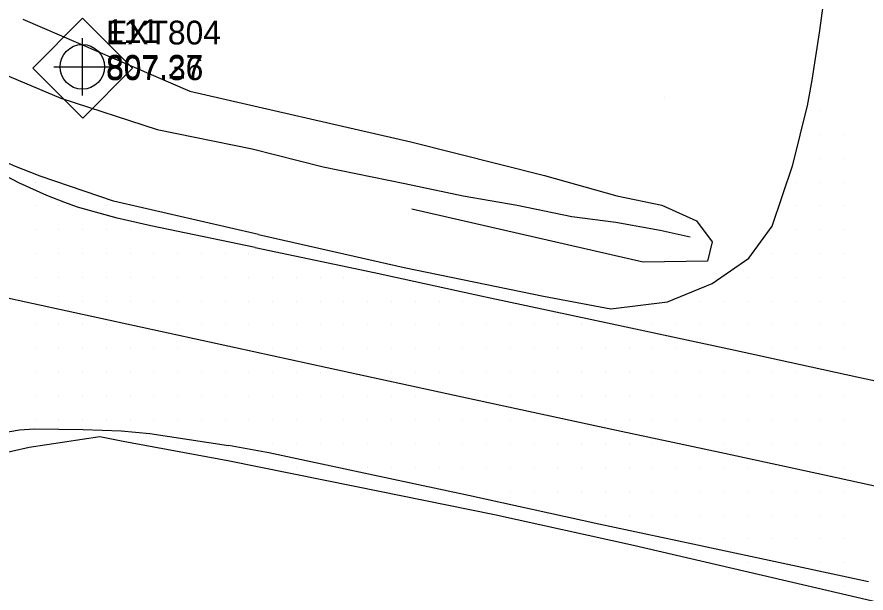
# Model space of a CAD drawing. Extents: x 1762120 to 1766775, y 709485 to 712965.
# Drawn here: x 1763911.9 to 1764001.2, y 712368.1 to 712428.6 of the extents above; entities that cross this region are included whole.
import ezdxf

# ---------------------------------------------------------------- set-up
doc = ezdxf.new("R2010")
doc.units = 0
for name, color, linetype in [('Cogo Default Point CELL', 7, 'Continuous'), ('COGO Default Point Elevation', 7, 'Continuous'), ('COGO Default Point Number', 7, 'Continuous'), ('CTL Secondary Horizontal and Vertical CELL', 7, 'Continuous'), ('CTL Secondary Horizontal and Vertical Cogo Elevation', 7, 'Continuous'), ('CTL Secondary Horizontal and Vertical Cogo Number', 7, 'Continuous'), ('Exist DTM QL2 LIDAR Elevation Point', 7, 'Continuous'), ('Exist DTM Scan Elevation Point', 7, 'Continuous'), ('Exist Roads EOP', 7, 'Continuous'), ('Exist Roads EOT', 7, 'Continuous'), ('PH Exist DTM Breakline', 7, 'Continuous')]:
    doc.layers.add(name, color=color, linetype=linetype)

msp = doc.modelspace()

# ---------------------------------------------------------------- linework, layer by layer
at = {"layer": 'Cogo Default Point CELL'}
for points in [[(1763918.724, 712426.379), (1763918.724, 712423.379)], [(1763915.724, 712423.379), (1763918.724, 712423.379)], [(1763918.724, 712423.379), (1763921.724, 712423.379)], [(1763918.724, 712423.379), (1763918.724, 712420.379)]]:
    msp.add_lwpolyline(points, dxfattribs=at)
msp.add_circle((1763918.724, 712423.379), 2.344, dxfattribs=at)
at = {"layer": 'CTL Secondary Horizontal and Vertical CELL'}
msp.add_line((1763918.73, 712423.23), (1763918.73, 712423.23), dxfattribs=at)
msp.add_lwpolyline([(1763913.515, 712423.248), (1763918.757, 712428.489), (1763924.007, 712423.239), (1763918.765, 712417.997)], close=True, dxfattribs=at)
at = {"layer": 'Exist DTM QL2 LIDAR Elevation Point'}
msp.add_line((1763979.981, 712420.146), (1763979.981, 712420.146), dxfattribs=at)
at = {"layer": 'Exist DTM Scan Elevation Point'}
for p, q in [((1763996.25, 712418.75), (1763996.25, 712418.75)), ((1763996.25, 712416.25), (1763996.25, 712416.25)), ((1763998.75, 712416.25), (1763998.75, 712416.25)), ((1763996.25, 712413.75), (1763996.25, 712413.75)), ((1763998.75, 712413.75), (1763998.75, 712413.75)), ((1763913.75, 712411.25), (1763913.75, 712411.25)), ((1763993.75, 712411.25), (1763993.75, 712411.25)), ((1763996.25, 712411.25), (1763996.25, 712411.25)), ((1763998.75, 712411.25), (1763998.75, 712411.25)), ((1763913.75, 712408.75), (1763913.75, 712408.75)), ((1763916.25, 712408.75), (1763916.25, 712408.75)), ((1763921.25, 712408.75), (1763921.25, 712408.75)), ((1763993.75, 712408.75), (1763993.75, 712408.75)), ((1763996.25, 712408.75), (1763996.25, 712408.75)), ((1763998.75, 712408.75), (1763998.75, 712408.75)), ((1763913.75, 712406.25), (1763913.75, 712406.25)), ((1763916.25, 712406.25), (1763916.25, 712406.25)), ((1763918.75, 712406.25), (1763918.75, 712406.25)), ((1763921.25, 712406.25), (1763921.25, 712406.25)), ((1763923.75, 712406.25), (1763923.75, 712406.25)), ((1763931.25, 712406.25), (1763931.25, 712406.25)), ((1763993.75, 712406.25), (1763993.75, 712406.25)), ((1763996.25, 712406.25), (1763996.25, 712406.25)), ((1763998.75, 712406.25), (1763998.75, 712406.25)), ((1763913.75, 712403.75), (1763913.75, 712403.75)), ((1763916.25, 712403.75), (1763916.25, 712403.75)), ((1763918.75, 712403.75), (1763918.75, 712403.75)), ((1763921.25, 712403.75), (1763921.25, 712403.75)), ((1763923.75, 712403.75), (1763923.75, 712403.75)), ((1763926.25, 712403.75), (1763926.25, 712403.75)), ((1763928.75, 712403.75), (1763928.75, 712403.75)), ((1763931.25, 712403.75), (1763931.25, 712403.75)), ((1763933.75, 712403.75), (1763933.75, 712403.75)), ((1763936.25, 712403.75), (1763936.25, 712403.75)), ((1763943.75, 712403.75), (1763943.75, 712403.75)), ((1763991.25, 712403.75), (1763991.25, 712403.75)), ((1763993.75, 712403.75), (1763993.75, 712403.75)), ((1763996.25, 712403.75), (1763996.25, 712403.75)), ((1763998.75, 712403.75), (1763998.75, 712403.75)), ((1763913.75, 712401.25), (1763913.75, 712401.25)), ((1763916.25, 712401.25), (1763916.25, 712401.25)), ((1763918.75, 712401.25), (1763918.75, 712401.25)), ((1763921.25, 712401.25), (1763921.25, 712401.25)), ((1763923.75, 712401.25), (1763923.75, 712401.25)), ((1763926.25, 712401.25), (1763926.25, 712401.25)), ((1763928.75, 712401.25), (1763928.75, 712401.25)), ((1763931.25, 712401.25), (1763931.25, 712401.25)), ((1763933.75, 712401.25), (1763933.75, 712401.25)), ((1763936.25, 712401.25), (1763936.25, 712401.25)), ((1763938.75, 712401.25), (1763938.75, 712401.25)), ((1763941.25, 712401.25), (1763941.25, 712401.25)), ((1763943.75, 712401.25), (1763943.75, 712401.25)), ((1763946.25, 712401.25), (1763946.25, 712401.25)), ((1763948.75, 712401.25), (1763948.75, 712401.25)), ((1763988.75, 712401.25), (1763988.75, 712401.25)), ((1763991.25, 712401.25), (1763991.25, 712401.25)), ((1763993.75, 712401.25), (1763993.75, 712401.25)), ((1763996.25, 712401.25), (1763996.25, 712401.25)), ((1763998.75, 712401.25), (1763998.75, 712401.25)), ((1763916.25, 712398.75), (1763916.25, 712398.75)), ((1763918.75, 712398.75), (1763918.75, 712398.75)), ((1763921.25, 712398.75), (1763921.25, 712398.75)), ((1763923.75, 712398.75), (1763923.75, 712398.75)), ((1763926.25, 712398.75), (1763926.25, 712398.75)), ((1763928.75, 712398.75), (1763928.75, 712398.75)), ((1763931.25, 712398.75), (1763931.25, 712398.75)), ((1763933.75, 712398.75), (1763933.75, 712398.75)), ((1763936.25, 712398.75), (1763936.25, 712398.75)), ((1763938.75, 712398.75), (1763938.75, 712398.75)), ((1763941.25, 712398.75), (1763941.25, 712398.75)), ((1763943.75, 712398.75), (1763943.75, 712398.75)), ((1763946.25, 712398.75), (1763946.25, 712398.75)), ((1763948.75, 712398.75), (1763948.75, 712398.75)), ((1763951.25, 712398.75), (1763951.25, 712398.75)), ((1763953.75, 712398.75), (1763953.75, 712398.75)), ((1763956.25, 712398.75), (1763956.25, 712398.75)), ((1763958.75, 712398.75), (1763958.75, 712398.75)), ((1763966.25, 712398.75), (1763966.25, 712398.75)), ((1763983.75, 712398.75), (1763983.75, 712398.75)), ((1763986.25, 712398.75), (1763986.25, 712398.75)), ((1763988.75, 712398.75), (1763988.75, 712398.75)), ((1763991.25, 712398.75), (1763991.25, 712398.75)), ((1763993.75, 712398.75), (1763993.75, 712398.75)), ((1763996.25, 712398.75), (1763996.25, 712398.75)), ((1763998.75, 712398.75), (1763998.75, 712398.75)), ((1763913.75, 712396.25), (1763913.75, 712396.25)), ((1763916.25, 712396.25), (1763916.25, 712396.25)), ((1763918.75, 712396.25), (1763918.75, 712396.25)), ((1763921.25, 712396.25), (1763921.25, 712396.25)), ((1763928.75, 712396.25), (1763928.75, 712396.25)), ((1763931.25, 712396.25), (1763931.25, 712396.25)), ((1763933.75, 712396.25), (1763933.75, 712396.25)), ((1763936.25, 712396.25), (1763936.25, 712396.25)), ((1763938.75, 712396.25), (1763938.75, 712396.25)), ((1763941.25, 712396.25), (1763941.25, 712396.25)), ((1763943.75, 712396.25), (1763943.75, 712396.25)), ((1763946.25, 712396.25), (1763946.25, 712396.25)), ((1763948.75, 712396.25), (1763948.75, 712396.25)), ((1763951.25, 712396.25), (1763951.25, 712396.25)), ((1763953.75, 712396.25), (1763953.75, 712396.25)), ((1763956.25, 712396.25), (1763956.25, 712396.25)), ((1763958.75, 712396.25), (1763958.75, 712396.25)), ((1763961.25, 712396.25), (1763961.25, 712396.25)), ((1763963.75, 712396.25), (1763963.75, 712396.25)), ((1763966.25, 712396.25), (1763966.25, 712396.25)), ((1763968.75, 712396.25), (1763968.75, 712396.25)), ((1763971.25, 712396.25), (1763971.25, 712396.25)), ((1763978.75, 712396.25), (1763978.75, 712396.25)), ((1763981.25, 712396.25), (1763981.25, 712396.25)), ((1763983.75, 712396.25), (1763983.75, 712396.25)), ((1763986.25, 712396.25), (1763986.25, 712396.25)), ((1763988.75, 712396.25), (1763988.75, 712396.25)), ((1763991.25, 712396.25), (1763991.25, 712396.25)), ((1763993.75, 712396.25), (1763993.75, 712396.25)), ((1763996.25, 712396.25), (1763996.25, 712396.25)), ((1763998.75, 712396.25), (1763998.75, 712396.25)), ((1763913.75, 712393.75), (1763913.75, 712393.75)), ((1763916.25, 712393.75), (1763916.25, 712393.75)), ((1763918.75, 712393.75), (1763918.75, 712393.75)), ((1763921.25, 712393.75), (1763921.25, 712393.75)), ((1763923.75, 712393.75), (1763923.75, 712393.75)), ((1763926.25, 712393.75), (1763926.25, 712393.75)), ((1763928.75, 712393.75), (1763928.75, 712393.75)), ((1763931.25, 712393.75), (1763931.25, 712393.75)), ((1763938.75, 712393.75), (1763938.75, 712393.75)), ((1763941.25, 712393.75), (1763941.25, 712393.75)), ((1763943.75, 712393.75), (1763943.75, 712393.75)), ((1763946.25, 712393.75), (1763946.25, 712393.75)), ((1763948.75, 712393.75), (1763948.75, 712393.75)), ((1763951.25, 712393.75), (1763951.25, 712393.75)), ((1763953.75, 712393.75), (1763953.75, 712393.75)), ((1763956.25, 712393.75), (1763956.25, 712393.75)), ((1763958.75, 712393.75), (1763958.75, 712393.75)), ((1763961.25, 712393.75), (1763961.25, 712393.75)), ((1763963.75, 712393.75), (1763963.75, 712393.75)), ((1763966.25, 712393.75), (1763966.25, 712393.75)), ((1763968.75, 712393.75), (1763968.75, 712393.75)), ((1763971.25, 712393.75), (1763971.25, 712393.75)), ((1763973.75, 712393.75), (1763973.75, 712393.75)), ((1763976.25, 712393.75), (1763976.25, 712393.75)), ((1763978.75, 712393.75), (1763978.75, 712393.75)), ((1763981.25, 712393.75), (1763981.25, 712393.75)), ((1763983.75, 712393.75), (1763983.75, 712393.75)), ((1763991.25, 712393.75), (1763991.25, 712393.75)), ((1763993.75, 712393.75), (1763993.75, 712393.75)), ((1763996.25, 712393.75), (1763996.25, 712393.75)), ((1763998.75, 712393.75), (1763998.75, 712393.75)), ((1763913.75, 712391.25), (1763913.75, 712391.25)), ((1763916.25, 712391.25), (1763916.25, 712391.25)), ((1763918.75, 712391.25), (1763918.75, 712391.25)), ((1763921.25, 712391.25), (1763921.25, 712391.25)), ((1763923.75, 712391.25), (1763923.75, 712391.25)), ((1763926.25, 712391.25), (1763926.25, 712391.25)), ((1763928.75, 712391.25), (1763928.75, 712391.25)), ((1763931.25, 712391.25), (1763931.25, 712391.25)), ((1763933.75, 712391.25), (1763933.75, 712391.25)), ((1763936.25, 712391.25), (1763936.25, 712391.25)), ((1763938.75, 712391.25), (1763938.75, 712391.25)), ((1763941.25, 712391.25), (1763941.25, 712391.25)), ((1763943.75, 712391.25), (1763943.75, 712391.25)), ((1763951.25, 712391.25), (1763951.25, 712391.25)), ((1763953.75, 712391.25), (1763953.75, 712391.25)), ((1763956.25, 712391.25), (1763956.25, 712391.25)), ((1763958.75, 712391.25), (1763958.75, 712391.25)), ((1763961.25, 712391.25), (1763961.25, 712391.25)), ((1763963.75, 712391.25), (1763963.75, 712391.25)), ((1763966.25, 712391.25), (1763966.25, 712391.25)), ((1763968.75, 712391.25), (1763968.75, 712391.25)), ((1763971.25, 712391.25), (1763971.25, 712391.25)), ((1763973.75, 712391.25), (1763973.75, 712391.25)), ((1763976.25, 712391.25), (1763976.25, 712391.25)), ((1763978.75, 712391.25), (1763978.75, 712391.25)), ((1763981.25, 712391.25), (1763981.25, 712391.25)), ((1763983.75, 712391.25), (1763983.75, 712391.25)), ((1763986.25, 712391.25), (1763986.25, 712391.25)), ((1763988.75, 712391.25), (1763988.75, 712391.25)), ((1763991.25, 712391.25), (1763991.25, 712391.25)), ((1763993.75, 712391.25), (1763993.75, 712391.25)), ((1763913.75, 712388.75), (1763913.75, 712388.75)), ((1763916.25, 712388.75), (1763916.25, 712388.75)), ((1763918.75, 712388.75), (1763918.75, 712388.75)), ((1763921.25, 712388.75), (1763921.25, 712388.75)), ((1763923.75, 712388.75), (1763923.75, 712388.75)), ((1763926.25, 712388.75), (1763926.25, 712388.75)), ((1763928.75, 712388.75), (1763928.75, 712388.75)), ((1763931.25, 712388.75), (1763931.25, 712388.75)), ((1763933.75, 712388.75), (1763933.75, 712388.75)), ((1763936.25, 712388.75), (1763936.25, 712388.75)), ((1763938.75, 712388.75), (1763938.75, 712388.75)), ((1763941.25, 712388.75), (1763941.25, 712388.75)), ((1763943.75, 712388.75), (1763943.75, 712388.75)), ((1763946.25, 712388.75), (1763946.25, 712388.75)), ((1763948.75, 712388.75), (1763948.75, 712388.75)), ((1763951.25, 712388.75), (1763951.25, 712388.75)), ((1763953.75, 712388.75), (1763953.75, 712388.75)), ((1763961.25, 712388.75), (1763961.25, 712388.75)), ((1763963.75, 712388.75), (1763963.75, 712388.75)), ((1763966.25, 712388.75), (1763966.25, 712388.75)), ((1763968.75, 712388.75), (1763968.75, 712388.75)), ((1763971.25, 712388.75), (1763971.25, 712388.75)), ((1763973.75, 712388.75), (1763973.75, 712388.75)), ((1763976.25, 712388.75), (1763976.25, 712388.75)), ((1763978.75, 712388.75), (1763978.75, 712388.75)), ((1763981.25, 712388.75), (1763981.25, 712388.75)), ((1763983.75, 712388.75), (1763983.75, 712388.75)), ((1763986.25, 712388.75), (1763986.25, 712388.75)), ((1763988.75, 712388.75), (1763988.75, 712388.75)), ((1763991.25, 712388.75), (1763991.25, 712388.75)), ((1763993.75, 712388.75), (1763993.75, 712388.75)), ((1763996.25, 712388.75), (1763996.25, 712388.75)), ((1763998.75, 712388.75), (1763998.75, 712388.75)), ((1763913.75, 712386.25), (1763913.75, 712386.25)), ((1763916.25, 712386.25), (1763916.25, 712386.25)), ((1763918.75, 712386.25), (1763918.75, 712386.25)), ((1763921.25, 712386.25), (1763921.25, 712386.25)), ((1763923.75, 712386.25), (1763923.75, 712386.25)), ((1763926.25, 712386.25), (1763926.25, 712386.25)), ((1763928.75, 712386.25), (1763928.75, 712386.25)), ((1763931.25, 712386.25), (1763931.25, 712386.25)), ((1763933.75, 712386.25), (1763933.75, 712386.25)), ((1763936.25, 712386.25), (1763936.25, 712386.25)), ((1763938.75, 712386.25), (1763938.75, 712386.25)), ((1763941.25, 712386.25), (1763941.25, 712386.25)), ((1763943.75, 712386.25), (1763943.75, 712386.25)), ((1763946.25, 712386.25), (1763946.25, 712386.25)), ((1763948.75, 712386.25), (1763948.75, 712386.25)), ((1763951.25, 712386.25), (1763951.25, 712386.25)), ((1763953.75, 712386.25), (1763953.75, 712386.25)), ((1763956.25, 712386.25), (1763956.25, 712386.25)), ((1763958.75, 712386.25), (1763958.75, 712386.25)), ((1763961.25, 712386.25), (1763961.25, 712386.25)), ((1763963.75, 712386.25), (1763963.75, 712386.25)), ((1763966.25, 712386.25), (1763966.25, 712386.25)), ((1763973.75, 712386.25), (1763973.75, 712386.25)), ((1763976.25, 712386.25), (1763976.25, 712386.25)), ((1763978.75, 712386.25), (1763978.75, 712386.25)), ((1763981.25, 712386.25), (1763981.25, 712386.25)), ((1763983.75, 712386.25), (1763983.75, 712386.25)), ((1763986.25, 712386.25), (1763986.25, 712386.25)), ((1763988.75, 712386.25), (1763988.75, 712386.25)), ((1763991.25, 712386.25), (1763991.25, 712386.25)), ((1763993.75, 712386.25), (1763993.75, 712386.25)), ((1763996.25, 712386.25), (1763996.25, 712386.25)), ((1763998.75, 712386.25), (1763998.75, 712386.25)), ((1763928.75, 712383.75), (1763928.75, 712383.75)), ((1763936.25, 712383.75), (1763936.25, 712383.75)), ((1763938.75, 712383.75), (1763938.75, 712383.75)), ((1763941.25, 712383.75), (1763941.25, 712383.75)), ((1763943.75, 712383.75), (1763943.75, 712383.75)), ((1763946.25, 712383.75), (1763946.25, 712383.75)), ((1763948.75, 712383.75), (1763948.75, 712383.75)), ((1763951.25, 712383.75), (1763951.25, 712383.75)), ((1763953.75, 712383.75), (1763953.75, 712383.75)), ((1763956.25, 712383.75), (1763956.25, 712383.75)), ((1763958.75, 712383.75), (1763958.75, 712383.75)), ((1763961.25, 712383.75), (1763961.25, 712383.75)), ((1763963.75, 712383.75), (1763963.75, 712383.75)), ((1763966.25, 712383.75), (1763966.25, 712383.75)), ((1763968.75, 712383.75), (1763968.75, 712383.75)), ((1763971.25, 712383.75), (1763971.25, 712383.75)), ((1763973.75, 712383.75), (1763973.75, 712383.75)), ((1763976.25, 712383.75), (1763976.25, 712383.75)), ((1763978.75, 712383.75), (1763978.75, 712383.75)), ((1763986.25, 712383.75), (1763986.25, 712383.75)), ((1763988.75, 712383.75), (1763988.75, 712383.75)), ((1763991.25, 712383.75), (1763991.25, 712383.75)), ((1763993.75, 712383.75), (1763993.75, 712383.75)), ((1763996.25, 712383.75), (1763996.25, 712383.75)), ((1763998.75, 712383.75), (1763998.75, 712383.75)), ((1763941.25, 712381.25), (1763941.25, 712381.25)), ((1763948.75, 712381.25), (1763948.75, 712381.25)), ((1763951.25, 712381.25), (1763951.25, 712381.25)), ((1763953.75, 712381.25), (1763953.75, 712381.25)), ((1763956.25, 712381.25), (1763956.25, 712381.25)), ((1763958.75, 712381.25), (1763958.75, 712381.25)), ((1763961.25, 712381.25), (1763961.25, 712381.25)), ((1763963.75, 712381.25), (1763963.75, 712381.25)), ((1763966.25, 712381.25), (1763966.25, 712381.25)), ((1763968.75, 712381.25), (1763968.75, 712381.25)), ((1763971.25, 712381.25), (1763971.25, 712381.25)), ((1763973.75, 712381.25), (1763973.75, 712381.25)), ((1763976.25, 712381.25), (1763976.25, 712381.25)), ((1763978.75, 712381.25), (1763978.75, 712381.25)), ((1763981.25, 712381.25), (1763981.25, 712381.25)), ((1763983.75, 712381.25), (1763983.75, 712381.25)), ((1763986.25, 712381.25), (1763986.25, 712381.25)), ((1763988.75, 712381.25), (1763988.75, 712381.25)), ((1763996.25, 712381.25), (1763996.25, 712381.25)), ((1763998.75, 712381.25), (1763998.75, 712381.25)), ((1763953.75, 712378.75), (1763953.75, 712378.75)), ((1763961.25, 712378.75), (1763961.25, 712378.75)), ((1763963.75, 712378.75), (1763963.75, 712378.75)), ((1763966.25, 712378.75), (1763966.25, 712378.75)), ((1763968.75, 712378.75), (1763968.75, 712378.75)), ((1763971.25, 712378.75), (1763971.25, 712378.75)), ((1763973.75, 712378.75), (1763973.75, 712378.75)), ((1763976.25, 712378.75), (1763976.25, 712378.75)), ((1763978.75, 712378.75), (1763978.75, 712378.75)), ((1763981.25, 712378.75), (1763981.25, 712378.75)), ((1763983.75, 712378.75), (1763983.75, 712378.75)), ((1763986.25, 712378.75), (1763986.25, 712378.75)), ((1763988.75, 712378.75), (1763988.75, 712378.75)), ((1763991.25, 712378.75), (1763991.25, 712378.75)), ((1763993.75, 712378.75), (1763993.75, 712378.75)), ((1763996.25, 712378.75), (1763996.25, 712378.75)), ((1763998.75, 712378.75), (1763998.75, 712378.75)), ((1763966.25, 712376.25), (1763966.25, 712376.25)), ((1763971.25, 712376.25), (1763971.25, 712376.25)), ((1763973.75, 712376.25), (1763973.75, 712376.25)), ((1763976.25, 712376.25), (1763976.25, 712376.25)), ((1763978.75, 712376.25), (1763978.75, 712376.25)), ((1763981.25, 712376.25), (1763981.25, 712376.25)), ((1763983.75, 712376.25), (1763983.75, 712376.25)), ((1763986.25, 712376.25), (1763986.25, 712376.25)), ((1763988.75, 712376.25), (1763988.75, 712376.25)), ((1763991.25, 712376.25), (1763991.25, 712376.25)), ((1763993.75, 712376.25), (1763993.75, 712376.25)), ((1763996.25, 712376.25), (1763996.25, 712376.25)), ((1763998.75, 712376.25), (1763998.75, 712376.25)), ((1763976.25, 712373.75), (1763976.25, 712373.75)), ((1763983.75, 712373.75), (1763983.75, 712373.75)), ((1763986.25, 712373.75), (1763986.25, 712373.75)), ((1763988.75, 712373.75), (1763988.75, 712373.75)), ((1763991.25, 712373.75), (1763991.25, 712373.75)), ((1763993.75, 712373.75), (1763993.75, 712373.75)), ((1763996.25, 712373.75), (1763996.25, 712373.75)), ((1763998.75, 712373.75), (1763998.75, 712373.75)), ((1763988.75, 712371.25), (1763988.75, 712371.25)), ((1763996.25, 712371.25), (1763996.25, 712371.25)), ((1763998.75, 712371.25), (1763998.75, 712371.25)), ((1763998.75, 712368.75), (1763998.75, 712368.75))]:
    msp.add_line(p, q, dxfattribs=at)
at = {"layer": 'Exist Roads EOP'}
for points in [[(1763937.27, 712405.74), (1763922, 712409.27), (1763914.3, 712411.89), (1763911.52, 712412.97), (1763907.31, 712414.92), (1763905.7, 712415.7), (1763904.88, 712417.5), (1763901.53, 712420.73), (1763892.75, 712429.99), (1763886.13, 712439.51), (1763884.183, 712443.669)], [(1763974.333, 712397.927), (1763980.3, 712398.665), (1763984.997, 712400.593), (1763988.846, 712403.258), (1763991.289, 712406.636), (1763993.481, 712413.079), (1763995.017, 712419.301)], [(1763937.27, 712405.74), (1763952.569, 712402.29), (1763967.246, 712399.269), (1763974.333, 712397.927)], [(1763934.045, 712381.948), (1763923.009, 712384.006), (1763920.567, 712384.464), (1763913.145, 712383.35), (1763909.379, 712382.508), (1763904.066, 712380.959), (1763901.156, 712379.529), (1763899.682, 712377.869), (1763897.304, 712375.885), (1763895.607, 712374.495), (1763894.665, 712373.129), (1763893.725, 712370.718), (1763892.719, 712368.183), (1763892.001, 712365.299), (1763891.368, 712360.754), (1763891.073, 712357.928), (1763891.057, 712351.383)], [(1764064.668, 712330.179), (1764064.854, 712330.245), (1764068.514, 712331.608), (1764069.587, 712332.629), (1764070.141, 712333.86), (1764069.865, 712336.332), (1764069.125, 712339.365), (1764068.178, 712342.188), (1764067.219, 712345.091), (1764065.818, 712347.808), (1764051.04, 712351.71), (1764036.514, 712355.552), (1764028.09, 712358.126), (1764020.547, 712362.975), (1764005.935, 712366.257), (1763991.324, 712369.661), (1763976.724, 712373.072), (1763962.071, 712376.273), (1763947.386, 712379.266), (1763934.045, 712381.948)]]:
    msp.add_lwpolyline(points, dxfattribs=at)
at = {"layer": 'Exist Roads EOT'}
for points in [[(1763936.9, 712404.39), (1763925.94, 712406.66), (1763922.4, 712407.48), (1763918.21, 712408.64), (1763916.89, 712409.12), (1763914.98, 712409.85), (1763912.11, 712411.15), (1763909.8, 712412.34), (1763907.51, 712413.59), (1763902.3, 712417.34), (1763899.48, 712420.04), (1763895.32, 712424.3), (1763892.72, 712427.36), (1763890.75, 712429.87), (1763889.19, 712432.14), (1763886.09, 712437.17), (1763884.49, 712440.43)], [(1763936.9, 712404.39), (1763949.432, 712401.765), (1763961.153, 712399.203), (1763974.456, 712396.373), (1763987.24, 712393.621), (1764000.212, 712390.795), (1764012.465, 712388.156), (1764026.205, 712385.101), (1764037.224, 712382.749), (1764049.265, 712380.14), (1764066.313, 712376.495), (1764083.445, 712372.764), (1764095.454, 712370.149), (1764109.306, 712367.155), (1764120.538, 712364.717), (1764131.502, 712362.333), (1764145.221, 712359.394), (1764154.889, 712357.364), (1764167.863, 712354.686), (1764175.23, 712353.101), (1764183.759, 712351.333), (1764196.566, 712348.502)], [(1763910.03, 712399.26), (1763934.85, 712393.88)], [(1763934.85, 712393.88), (1763944.479, 712391.773), (1763958.695, 712388.702), (1763974.939, 712385.195), (1763986.293, 712382.776), (1763996.812, 712380.495), (1764022.245, 712374.912), (1764038.571, 712371.473), (1764049.555, 712369.081), (1764063.415, 712366.068), (1764079.739, 712362.586), (1764092.609, 712359.852), (1764108.103, 712356.47), (1764121.783, 712353.589), (1764136.909, 712350.3), (1764153.18, 712346.875), (1764169.623, 712343.331), (1764181.305, 712340.815), (1764211.754, 712334.157), (1764222.045, 712332.077)], [(1763894.29, 712375.12), (1763898.67, 712379.54), (1763899.94, 712380.53), (1763904.8, 712383.48), (1763906.8, 712384.13), (1763908.81, 712384.61), (1763910.06, 712384.85), (1763912.13, 712385.21), (1763913.71, 712385.33), (1763918.81, 712385.26), (1763922.82, 712385.1), (1763925.83, 712384.83), (1763934.114, 712383.564)], [(1764001.432, 712369.231), (1763993.43, 712370.947), (1763982.941, 712373.206), (1763973.078, 712375.313), (1763959.351, 712378.302), (1763948.331, 712380.674), (1763938.362, 712382.805), (1763934.114, 712383.564)]]:
    msp.add_lwpolyline(points, dxfattribs=at)
at = {"layer": 'PH Exist DTM Breakline'}
for points in [[(1763887.598, 712457.067), (1763888.297, 712452.424), (1763890.798, 712445.877), (1763893.88, 712438.461), (1763896.87, 712433.203), (1763899.913, 712429.006), (1763902.307, 712426.624), (1763908.119, 712423.59), (1763916.457, 712420.088), (1763926.606, 712416.801), (1763936.591, 712414.759), (1763944.064, 712412.865), (1763952.639, 712411.118), (1763958.807, 712409.813), (1763964.456, 712408.822), (1763970.211, 712407.63), (1763974.866, 712407.043), (1763979.52, 712406.22), (1763982.686, 712405.505)], [(1763995, 712419.265), (1763995.505, 712421.974), (1763996.309, 712427.209), (1763996.852, 712431.121)], [(1763912.454, 712428.378), (1763930.048, 712420.835), (1763953.297, 712415.494), (1763967.361, 712411.955), (1763974.97, 712409.814), (1763979.68, 712408.851), (1763983.351, 712407.184), (1763984.989, 712404.992), (1763984.479, 712402.951), (1763977.731, 712402.839), (1763953.386, 712408.407)]]:
    msp.add_lwpolyline(points, dxfattribs=at)

# ---------------------------------------------------------------- texts
at = {"layer": 'COGO Default Point Elevation'}
msp.add_text('807.27', height=2.5, dxfattribs=at).set_placement((1763921.224, 712422.129))
at = {"layer": 'COGO Default Point Number'}
msp.add_text('111', height=2.5, dxfattribs=at).set_placement((1763921.224, 712425.879))
at = {"layer": 'CTL Secondary Horizontal and Vertical Cogo Elevation'}
msp.add_text('807.36', height=2.5, dxfattribs=at).set_placement((1763921.23, 712421.98))
at = {"layer": 'CTL Secondary Horizontal and Vertical Cogo Number'}
msp.add_text('EXT804', height=2.5, dxfattribs=at).set_placement((1763921.23, 712425.73))

doc.saveas('drawing.dxf')
